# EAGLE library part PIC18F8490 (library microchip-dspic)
PIC18F Flash Microcontroller with LCD driver
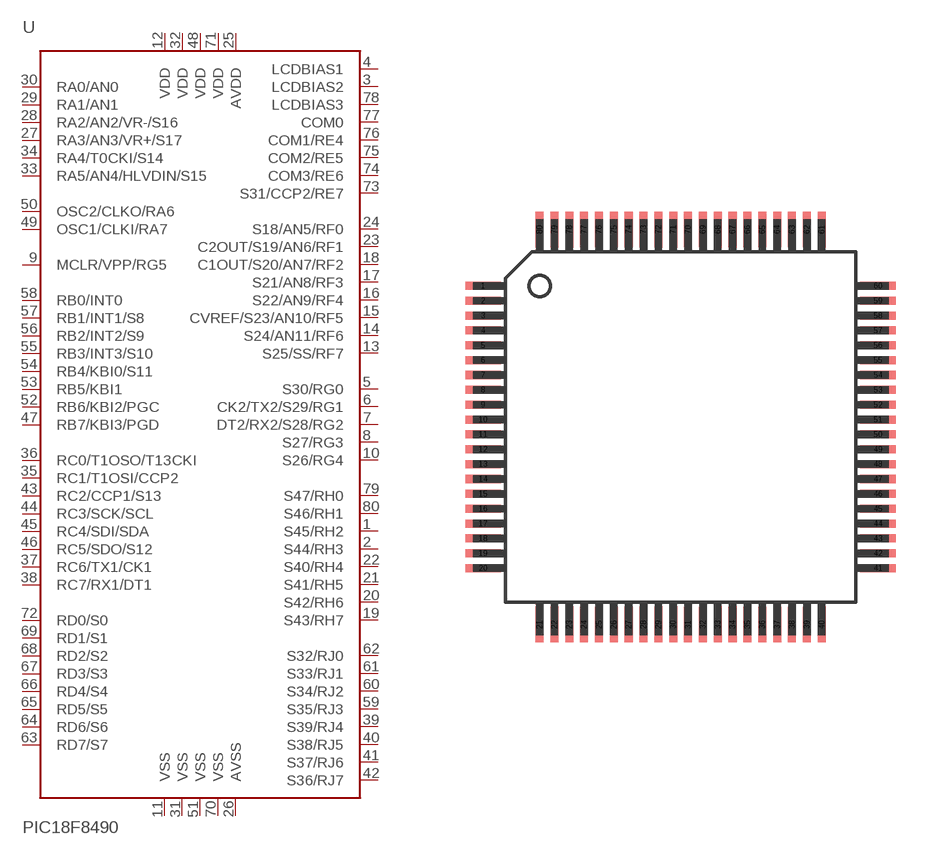
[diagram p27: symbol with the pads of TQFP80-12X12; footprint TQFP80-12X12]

Designator prefix -

## PIC18F8490TQ-80  [TQFP80-12X12]
1  S45/RH2
2  S44/RH3
3  LCDBIAS2  in
4  LCDBIAS1  in
5  S30/RG0
6  CK2/TX2/S29/RG1
7  DT2/RX2/S28/RG2
8  S27/RG3
9  MCLR/VPP/RG5  in
10  S26/RG4
11  VSS  pwr
12  VDD  pwr
13  S25/SS/RF7
14  S24/AN11/RF6
15  CVREF/S23/AN10/RF5
16  S22/AN9/RF4
17  S21/AN8/RF3
18  C1OUT/S20/AN7/RF2
19  S43/RH7
20  S42/RH6
21  S41/RH5
22  S40/RH4
23  C2OUT/S19/AN6/RF1
24  S18/AN5/RF0
25  AVDD  pwr
26  AVSS  pwr
27  RA3/AN3/VR+/S17
28  RA2/AN2/VR-/S16
29  RA1/AN1
30  RA0/AN0
31  VSS  pwr
32  VDD  pwr
33  RA5/AN4/HLVDIN/S15
34  RA4/T0CKI/S14
35  RC1/T1OSI/CCP2
36  RC0/T1OSO/T13CKI
37  RC6/TX1/CK1
38  RC7/RX1/DT1
39  S39/RJ4
40  S38/RJ5
41  S37/RJ6
42  S36/RJ7
43  RC2/CCP1/S13
44  RC3/SCK/SCL
45  RC4/SDI/SDA
46  RC5/SDO/S12
47  RB7/KBI3/PGD
48  VDD  pwr
49  OSC1/CLKI/RA7
50  OSC2/CLKO/RA6
51  VSS  pwr
52  RB6/KBI2/PGC
53  RB5/KBI1
54  RB4/KBI0/S11
55  RB3/INT3/S10
56  RB2/INT2/S9
57  RB1/INT1/S8
58  RB0/INT0
59  S35/RJ3
60  S34/RJ2
61  S33/RJ1
62  S32/RJ0
63  RD7/S7
64  RD6/S6
65  RD5/S5
66  RD4/S4
67  RD3/S3
68  RD2/S2
69  RD1/S1
70  VSS  pwr
71  VDD  pwr
72  RD0/S0
73  S31/CCP2/RE7
74  COM3/RE6
75  COM2/RE5
76  COM1/RE4
77  COM0  out
78  LCDBIAS3  in
79  S47/RH0
80  S46/RH1

## Footprint TQFP80-12X12 (pad centres in mm)
Thin Quad Flat Pack
smd 1.2 x 0.27: 1 -6.65,4.75; 2 -6.65,4.25; 3 -6.65,3.75; 4 -6.65,3.25; 5 -6.65,2.75; 6 -6.65,2.25; 7 -6.65,1.75; 8 -6.65,1.25; 9 -6.65,0.75; 10 -6.65,0.25; 11 -6.65,-0.25; 12 -6.65,-0.75; 13 -6.65,-1.25; 14 -6.65,-1.75; 15 -6.65,-2.25; 16 -6.65,-2.75; 17 -6.65,-3.25; 18 -6.65,-3.75; 19 -6.65,-4.25; 20 -6.65,-4.75; 41 6.65,-4.75; 42 6.65,-4.25; 43 6.65,-3.75; 44 6.65,-3.25; 45 6.65,-2.75; 46 6.65,-2.25; 47 6.65,-1.75; 48 6.65,-1.25; 49 6.65,-0.75; 50 6.65,-0.25; 51 6.65,0.25; 52 6.65,0.75; 53 6.65,1.25; 54 6.65,1.75; 55 6.65,2.25; 56 6.65,2.75; 57 6.65,3.25; 58 6.65,3.75; 59 6.65,4.25; 60 6.65,4.75
smd 0.27 x 1.2: 21 -4.75,-6.65; 22 -4.25,-6.65; 23 -3.75,-6.65; 24 -3.25,-6.65; 25 -2.75,-6.65; 26 -2.25,-6.65; 27 -1.75,-6.65; 28 -1.25,-6.65; 29 -0.75,-6.65; 30 -0.25,-6.65; 31 0.25,-6.65; 32 0.75,-6.65; 33 1.25,-6.65; 34 1.75,-6.65; 35 2.25,-6.65; 36 2.75,-6.65; 37 3.25,-6.65; 38 3.75,-6.65; 39 4.25,-6.65; 40 4.75,-6.65; 61 4.75,6.65; 62 4.25,6.65; 63 3.75,6.65; 64 3.25,6.65; 65 2.75,6.65; 66 2.25,6.65; 67 1.75,6.65; 68 1.25,6.65; 69 0.75,6.65; 70 0.25,6.65; 71 -0.25,6.65; 72 -0.75,6.65; 73 -1.25,6.65; 74 -1.75,6.65; 75 -2.25,6.65; 76 -2.75,6.65; 77 -3.25,6.65; 78 -3.75,6.65; 79 -4.25,6.65; 80 -4.75,6.65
